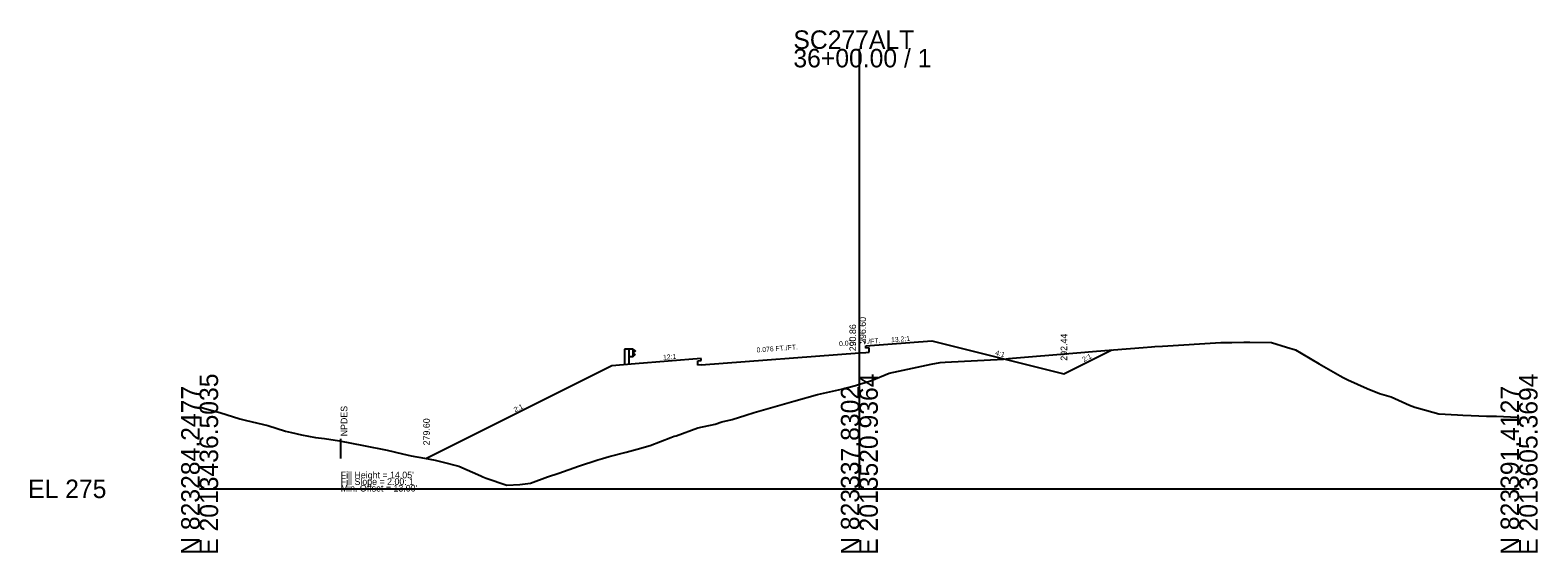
# Model space of a CAD drawing. Extents: x 205929 to 2357175, y -1785700 to 827636.
# Drawn here: x 2018394.5 to 2018623, y 824034.6 to 824113.8 of the extents above; entities that cross this region are included whole.
import ezdxf

# ---------------------------------------------------------------- set-up
doc = ezdxf.new("R2010")
doc.units = 0
for name, color, linetype in [('RD_GPK_XS_Cell', 7, 'Continuous'), ('RD_XS_Base', 7, 'Continuous'), ('RD_XS_EarthShd', 7, 'Continuous'), ('RD_XS_ExGround', 7, 'Continuous'), ('RD_XS_GR', 7, 'Continuous'), ('RD_XS_NPDES', 7, 'Continuous'), ('RD_XS_Pave', 7, 'Continuous'), ('RD_XS_TieSlope', 7, 'Continuous'), ('RD_XS_TX_Elev_EX', 7, 'Continuous'), ('RD_XS_TX_Elev_PR', 7, 'Continuous'), ('RD_XS_TX_ShdSlope', 7, 'Continuous'), ('RD_XS_TX_Slope', 7, 'Continuous'), ('RD_XS_TX_Warning', 7, 'Continuous')]:
    doc.layers.add(name, color=color, linetype=linetype)

msp = doc.modelspace()

# ---------------------------------------------------------------- linework, layer by layer
at = {"layer": 'RD_GPK_XS_Cell'}
for p, q in [((2018520.17, 824044.26), (2018520.17, 824110.95)), ((2018420.17, 824044.26), (2018520.17, 824044.26)), ((2018520.17, 824044.26), (2018620.17, 824044.26))]:
    msp.add_line(p, q, dxfattribs=at)
at = {"layer": 'RD_XS_Base'}
for p, q in [((2018496.17, 824063.04), (2018520.17, 824064.86)), ((2018520.17, 824064.86), (2018521.17, 824064.93))]:
    msp.add_line(p, q, dxfattribs=at)
at = {"layer": 'RD_XS_EarthShd'}
for p, q in [((2018521.17, 824065.93), (2018531.17, 824066.69)), ((2018496.17, 824064.04), (2018486.17, 824063.21)), ((2018486.17, 824063.21), (2018482.67, 824062.91))]:
    msp.add_line(p, q, dxfattribs=at)
at = {"layer": 'RD_XS_ExGround'}
msp.add_lwpolyline([(2018420.17, 824056.68), (2018421.33, 824056.35), (2018423.24, 824055.83), (2018426.26, 824054.88), (2018427.25, 824054.6), (2018430.49, 824053.85), (2018433.17, 824053.03), (2018434.11, 824052.81), (2018435.59, 824052.45), (2018437.74, 824052.04), (2018439.09, 824051.88), (2018441.36, 824051.55), (2018445.02, 824050.81), (2018448.6, 824050.12), (2018450.94, 824049.55), (2018452.23, 824049.28), (2018454.26, 824048.92), (2018455.85, 824048.62), (2018456.86, 824048.36), (2018459.47, 824047.72), (2018462.78, 824046.23), (2018463.09, 824046.09), (2018463.59, 824045.9), (2018466.72, 824044.8), (2018468.7, 824044.92), (2018470.34, 824045.13), (2018472.92, 824046.07), (2018474.63, 824046.66), (2018477.59, 824047.69), (2018480.55, 824048.67), (2018481.21, 824048.88), (2018482.25, 824049.17), (2018484.83, 824049.82), (2018486.47, 824050.26), (2018488.45, 824050.83), (2018491.58, 824052.04), (2018492.08, 824052.23), (2018492.39, 824052.31), (2018495.7, 824053.49), (2018498.31, 824054.09), (2018499.32, 824054.4), (2018500.91, 824054.78), (2018502.95, 824055.45), (2018504.24, 824055.84), (2018510.24, 824057.55), (2018513.81, 824058.58), (2018516.08, 824059.05), (2018517.44, 824059.37), (2018519.58, 824059.94), (2018520.17, 824060.12), (2018521.06, 824060.37), (2018522, 824060.71), (2018524.68, 824061.79), (2018531.03, 824063.14), (2018532.41, 824063.41), (2018533.19, 824063.45), (2018542.01, 824063.94), (2018542.78, 824064), (2018553.14, 824064.89), (2018556.1, 824065.13), (2018563.17, 824065.69), (2018564.45, 824065.79), (2018564.98, 824065.84), (2018566.13, 824065.91), (2018574.95, 824066.47), (2018576.62, 824066.47), (2018578.44, 824066.49), (2018579.38, 824066.49), (2018582.65, 824066.44), (2018584.9, 824065.72), (2018586.27, 824065.34), (2018587.14, 824064.84), (2018589.89, 824063.19), (2018593.06, 824061.38), (2018593.51, 824061.13), (2018594.23, 824060.79), (2018597.14, 824059.49), (2018598.99, 824058.74), (2018600.76, 824058.22), (2018603.56, 824056.97), (2018604.38, 824056.65), (2018604.91, 824056.47), (2018608.01, 824055.64), (2018610.83, 824055.46), (2018611.63, 824055.41), (2018612.89, 824055.37), (2018615.25, 824055.29), (2018616.75, 824055.28), (2018618.87, 824055.2), (2018620.17, 824055.13)], dxfattribs=at)
at = {"layer": 'RD_XS_GR'}
for p, q in [((2018484.57, 824065.46), (2018484.57, 824063.07)), ((2018485.24, 824065.46), (2018484.57, 824065.46)), ((2018485.24, 824065.46), (2018485.24, 824063.13)), ((2018485.9, 824065.46), (2018485.24, 824065.46)), ((2018485.9, 824064.29), (2018485.24, 824064.29)), ((2018485.9, 824064.29), (2018485.9, 824065.46)), ((2018485.9, 824065.38), (2018486.17, 824065.18)), ((2018486.17, 824065.13), (2018485.9, 824064.93)), ((2018486.17, 824064.61), (2018485.9, 824064.81)), ((2018485.9, 824064.36), (2018486.17, 824064.56)), ((2018486.17, 824065.18), (2018486.17, 824065.13)), ((2018486.17, 824064.56), (2018486.17, 824064.61))]:
    msp.add_line(p, q, dxfattribs=at)
at = {"layer": 'RD_XS_NPDES'}
msp.add_line((2018441.56, 824048.86), (2018441.56, 824051.86), dxfattribs=at)
at = {"layer": 'RD_XS_Pave'}
for p, q in [((2018521.17, 824065.6), (2018521.17, 824065.93)), ((2018495.67, 824063.67), (2018496.17, 824063.71)), ((2018495.67, 824063), (2018495.67, 824063.67)), ((2018496.17, 824063.71), (2018496.17, 824064.04)), ((2018521.67, 824065.64), (2018521.17, 824065.6)), ((2018521.17, 824064.93), (2018521.67, 824064.97)), ((2018521.67, 824064.97), (2018521.67, 824065.64)), ((2018496.17, 824063.04), (2018495.67, 824063))]:
    msp.add_line(p, q, dxfattribs=at)
at = {"layer": 'RD_XS_TieSlope'}
for p, q in [((2018531.17, 824066.69), (2018551.17, 824061.69)), ((2018551.17, 824061.69), (2018558.42, 824065.32)), ((2018482.67, 824062.91), (2018454.56, 824048.86))]:
    msp.add_line(p, q, dxfattribs=at)

# ---------------------------------------------------------------- texts
at = {"layer": 'RD_GPK_XS_Cell'}
for s, p in [('SC277ALT', (2018510.17, 824110.95)), ('36+00.00 / 1', (2018510.17, 824108.15)), ('EL 275', (2018394.17, 824042.86))]:
    msp.add_text(s, height=2.8, dxfattribs=at).set_placement(p)
for s, p in [('E 2013436.5035', (2018422.97, 824034.26)), ('E 2013520.9364', (2018522.97, 824034.26)), ('E 2013605.3694', (2018622.97, 824034.26)), ('N 823284.2477', (2018420.17, 824034.26)), ('N 823337.8302', (2018520.17, 824034.26)), ('N 823391.4127', (2018620.17, 824034.26))]:
    msp.add_text(s, height=2.8, rotation=90, dxfattribs=at).set_placement(p)
at = {"layer": 'RD_XS_TX_Elev_EX'}
msp.add_text('290.86', height=1, rotation=90, dxfattribs=at).set_placement((2018519.67, 824065.12))
at = {"layer": 'RD_XS_TX_Elev_PR'}
for s, p in [(' 296.60', (2018521.17, 824065.86)), ('292.44', (2018551.67, 824063.69)), ('279.60', (2018455.06, 824050.86))]:
    msp.add_text(s, height=1, rotation=90, dxfattribs=at).set_placement(p)
at = {"layer": 'RD_XS_TX_ShdSlope'}
for s, rotation, p in [('13.2:1', 4.3347, (2018525, 824066.48)), ('12:1', 4.7636, (2018490.44, 824063.81))]:
    msp.add_text(s, height=0.75, rotation=rotation, dxfattribs=at).set_placement(p)
at = {"layer": 'RD_XS_TX_Slope'}
for s, rotation, p in [('0.076 FT./FT.', 4.3347, (2018504.62, 824064.93)), ('0.076 FT./FT.', 4.3347, (2018517.12, 824065.88)), ('4:1', 345.9638, (2018540.72, 824064.56)), ('2:1', 26.5651, (2018554.18, 824063.48)), ('2:1', 26.5651, (2018468, 824055.86))]:
    msp.add_text(s, height=0.75, rotation=rotation, dxfattribs=at).set_placement(p)
at = {"layer": 'RD_XS_TX_Warning'}
msp.add_text(' NPDES', height=1, rotation=90, dxfattribs=at).set_placement((2018442.56, 824051.86))
for s, p in [("Fill Height = 14.05' ", (2018441.56, 824045.86)), ('Fill Slope = 2.00: 1', (2018441.56, 824044.86)), ("Min. Offset = 13.00' ", (2018441.56, 824043.86))]:
    msp.add_text(s, height=1, dxfattribs=at).set_placement(p)

doc.saveas('drawing.dxf')
